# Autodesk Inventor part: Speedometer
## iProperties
Manager: Lebovitz
Company: Autodesk
Shininess: 64.0
Length Units: 11272
Angle Units: 11279
Time Units: 11290
Mass Units: 11286
Length Display Precision: 3
Angle Display Precision: 2
Compacted: True
Part Number: Speedometer
Document SubType Name: Modeling
Created: 2002-09
Designer: The PD Team
Project: Inventor Samples
Density: 0.0
Volumn: 0.0
Area: 0.0
PropertySet Name: Model Information
Control State: 0
Master: False
Checked Out: False
Author: The PD Team
Revision Number: A
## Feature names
1. Fillet1
2. Split3
3. Split4
4. Split5
5. Split6
6. Split7
7. Split8
8. Split9
9. Split10
10. Split11
11. Fillet5
12. Fillet8
13. Fillet9
14. Fillet10
15. Extrusion1
16. Extrusion2
17. Fillet2
18. Fillet3
